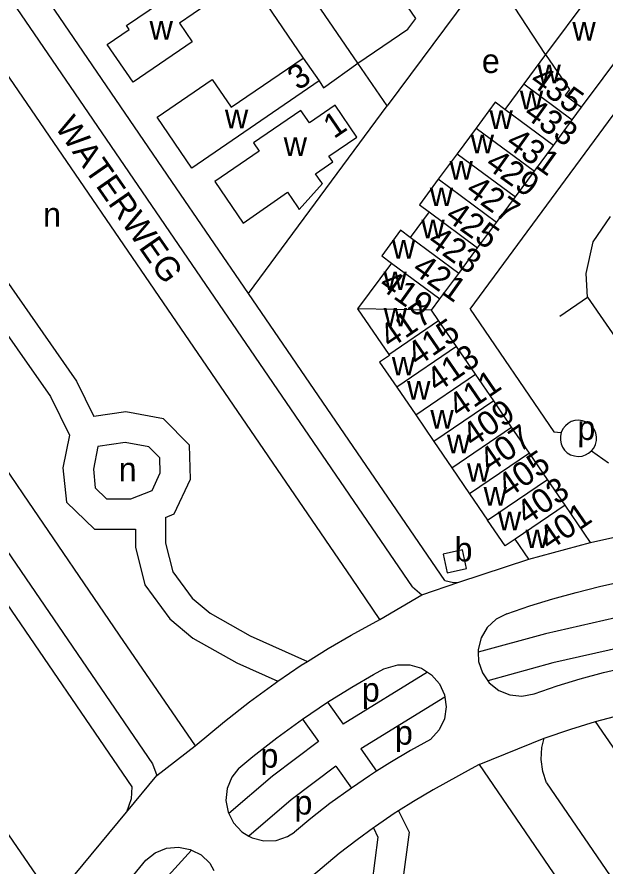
# Model space of a CAD drawing. Extents: x 154320 to 156262, y 382651 to 384180.
# Drawn here: x 155678.1 to 155775.5, y 383138.5 to 383279.2 of the extents above; entities that cross this region are included whole.
import ezdxf

# ---------------------------------------------------------------- set-up
doc = ezdxf.new("R2010")
doc.units = 0
for name, color, linetype in [('BLT_Basislijn', 7, 'Continuous'), ('BLT_Bebouwing', 7, 'Continuous'), ('BLT_Centroide', 7, 'Continuous'), ('BLT_Huisnummer', 7, 'Continuous'), ('BLT_Huisnummer_ tussenligend', 7, 'Continuous'), ('BLT_Onderdoorgang_en_onderverdeling', 7, 'Continuous'), ('BLT_Onderverdeling_panden', 7, 'Continuous'), ('BLT_Straatnaam', 7, 'Continuous'), ('BLT_Vlakafsluiter', 7, 'Continuous')]:
    doc.layers.add(name, color=color, linetype=linetype)

msp = doc.modelspace()

# ---------------------------------------------------------------- linework, layer by layer
at = {"layer": 'BLT_Basislijn'}
for p, q in [((155692.64, 383320.53), (155725.53, 383272.42)), ((155734.58, 383271.59), (155717.76, 383296.2)), ((155765.68, 383273), (155756.32, 383287.28)), ((155716.48, 383233.38), (155739.44, 383264.48)), ((155636.48, 383262.51), (155679.1, 383200.17)), ((155748.98, 383185.83), (155716.48, 383233.38)), ((155768.04, 383229.65), (155772.65, 383232.81)), ((155772.65, 383232.81), (155783.95, 383216.3)), ((155773.27, 383207.3), (155776.13, 383205.34)), ((155773.14, 383192.15), (155790.01, 383195.94)), ((155674.04, 383194.27), (155700.59, 383155.44)), ((155670.14, 383191.12), (155697.12, 383151.65)), ((155743.62, 383184.81), (155745.16, 383183.45)), ((155653.33, 383177.6), (155684.15, 383132.85)), ((155725.43, 383162.87), (155729.57, 383165.67)), ((155729.57, 383165.67), (155732.17, 383162.01)), ((155725.43, 383162.87), (155728.05, 383159.17)), ((155735.06, 383157.92), (155737.68, 383154.22)), ((155700.59, 383155.44), (155701.29, 383153.51)), ((155730.94, 383155.08), (155733.52, 383151.44)), ((155696.27, 383147.42), (155701.29, 383153.51)), ((155684.15, 383132.85), (155696.27, 383147.42)), ((155577.92, 382991.91), (155699.45, 383139.48))]:
    msp.add_line(p, q, dxfattribs=at)
for points in [[(155703.78, 383251.95), (155662.78, 383311.94)], [(155733.58, 383186.21), (155650, 383308.48)], [(155743.62, 383184.81), (155658.65, 383309.12)], [(155753.19, 383230.79), (155780.13, 383267.37), (155800.12, 383273.73)], [(155728.15, 383268.63), (155728.89, 383267.49), (155734.58, 383271.59)], [(155716.48, 383233.38), (155703.78, 383251.95)], [(155772.65, 383232.81), (155772.43, 383236.69), (155773.55, 383241.95), (155776.41, 383246.18)], [(155671.55, 383242.34), (155687.98, 383218.88), (155690.87, 383213)], [(155667.45, 383239.48), (155683.66, 383216.32), (155686.81, 383209.93), (155685.72, 383204.53), (155686.3, 383198.84), (155690.95, 383194.35), (155697.74, 383194.35)], [(155753.19, 383230.79), (155767.05, 383210.45), (155768.28, 383210.38)], [(155702.74, 383196.3), (155704.18, 383196.87), (155706.88, 383202.64), (155706.72, 383208.29), (155702.36, 383212.65), (155696.12, 383213.76), (155690.87, 383213)], [(155773.78, 383210.81), (155773.45, 383211.3), (155773, 383211.74), (155772.45, 383212.09), (155771.82, 383212.32), (155771.16, 383212.4), (155770.52, 383212.34), (155769.94, 383212.16), (155769.43, 383211.88), (155768.96, 383211.49), (155768.56, 383210.98), (155768.28, 383210.38)], [(155768.28, 383210.38), (155768.13, 383209.73), (155768.13, 383209.07), (155768.26, 383208.46), (155768.5, 383207.92)], [(155773.27, 383207.3), (155773.66, 383207.79), (155773.95, 383208.38), (155774.1, 383209.02), (155774.11, 383209.66), (155774, 383210.27), (155773.78, 383210.81)], [(155691.53, 383208.05), (155690.77, 383204.28), (155691.09, 383201.17), (155692.97, 383199.35), (155696.95, 383199.35), (155700.49, 383200.77), (155701.85, 383203.69), (155701.78, 383206.16), (155699.94, 383208), (155696.04, 383208.7), (155691.53, 383208.05)], [(155768.5, 383207.92), (155768.83, 383207.44), (155769.28, 383207.01), (155769.83, 383206.68), (155770.45, 383206.47), (155771.1, 383206.39), (155771.73, 383206.45), (155772.3, 383206.64), (155772.81, 383206.91), (155773.27, 383207.3)], [(155679.1, 383200.17), (155695.07, 383176.8)], [(155759.27, 383180.32), (155763.06, 383181.61), (155766.88, 383182.79), (155770.73, 383183.86), (155774.62, 383184.83), (155777.81, 383185.54), (155844.27, 383200.42)], [(155702.74, 383196.3), (155702.74, 383192), (155703.92, 383187.26), (155707.12, 383182.93), (155710.1, 383180.4), (155716.76, 383176.68), (155726.25, 383172.43)], [(155846.89, 383196.56), (155813.68, 383189.19), (155777.25, 383179.66), (155765.68, 383177.02), (155754.53, 383173.95)], [(155697.74, 383194.35), (155697.74, 383191.38), (155699.31, 383185.09), (155703.44, 383179.5), (155707.23, 383176.27), (155714.52, 383172.21), (155721.34, 383169.15)], [(155849.92, 383192.11), (155814.86, 383184.33), (155778.44, 383174.8), (155766.9, 383172.17), (155756.12, 383169.2)], [(155751.32, 383185.54), (155762.89, 383189.38)], [(155763.8, 383167.07), (155767.59, 383168.36), (155771.42, 383169.53), (155775.28, 383170.58), (155780.77, 383171.85), (155852.75, 383187.97)], [(155738.25, 383179.38), (155733.58, 383186.21)], [(155745.16, 383183.45), (155751.32, 383185.54)], [(155748.98, 383185.83), (155750.45, 383185.52), (155751.32, 383185.54)], [(155726.25, 383172.43), (155729.68, 383174.58), (155733.48, 383176.79), (155738.25, 383179.38)], [(155759.27, 383180.32), (155757.48, 383179.42), (155756.02, 383178.07), (155755, 383176.35), (155754.52, 383174.4), (155754.53, 383173.95)], [(155695.07, 383176.8), (155707.64, 383158.42)], [(155754.53, 383173.95), (155754.57, 383172.4), (155755.22, 383170.51), (155756.12, 383169.2)], [(155721.34, 383169.15), (155725.22, 383171.78), (155726.25, 383172.43)], [(155729.57, 383165.67), (155733.56, 383168.16), (155737.16, 383170.25), (155738.88, 383171.18)], [(155746.11, 383170.63), (155732.17, 383162.01)], [(155738.88, 383171.18), (155741.19, 383171.86), (155743.19, 383171.85), (155745.11, 383171.28), (155746.11, 383170.63)], [(155746.11, 383170.63), (155746.79, 383170.2), (155748.11, 383168.69), (155748.93, 383166.87), (155748.98, 383166.52)], [(155756.12, 383169.2), (155756.35, 383168.86), (155757.92, 383167.63), (155759.78, 383166.88), (155761.77, 383166.67), (155763.8, 383167.07)], [(155707.64, 383158.42), (155712.48, 383162.49), (155716.62, 383165.74), (155720.87, 383168.83), (155721.34, 383169.15)], [(155748.98, 383166.52), (155735.06, 383157.92)], [(155748.98, 383166.52), (155749.21, 383164.89), (155748.91, 383162.91), (155748.06, 383161.1), (155746.63, 383159.48)], [(155773.94, 383162.44), (155777.11, 383163.3), (155779.64, 383163.89)], [(155714.88, 383154.71), (155717.21, 383156.67), (155721.14, 383159.75), (155725.43, 383162.87)], [(155765.45, 383159.71), (155769.89, 383161.22), (155773.94, 383162.44)], [(155801.33, 383108.62), (155805.57, 383112.09), (155806.74, 383114.83), (155773.94, 383162.44)], [(155746.63, 383159.48), (155743.32, 383157.64), (155739.87, 383155.61), (155737.68, 383154.22)], [(155765.85, 383152.28), (155765.21, 383154.18), (155764.96, 383156.16), (155765.07, 383158.16), (155765.45, 383159.71)], [(155728.05, 383159.17), (155720.42, 383153.38), (155713.2, 383147.21)], [(155754.67, 383155.35), (155753.34, 383154.61)], [(155754.67, 383155.35), (155781.59, 383115.97), (155786.38, 383110.5), (155792.35, 383105.37), (155799.06, 383101.19), (155805.08, 383098.89), (155853.42, 383081.31)], [(155714.88, 383154.71), (155713.7, 383153.24), (155712.94, 383151.39), (155712.72, 383149.4), (155713.09, 383147.43), (155713.2, 383147.21)], [(155730.94, 383155.08), (155723.56, 383149.48), (155716.55, 383143.49)], [(155737.68, 383154.22), (155736.49, 383153.46), (155733.52, 383151.44)], [(155753.34, 383154.61), (155747.04, 383151.13), (155743.79, 383149.21), (155741.32, 383147.65)], [(155765.85, 383152.28), (155787.53, 383120.57), (155791.67, 383115.84), (155796.8, 383111.44), (155801.33, 383108.62)], [(155697.12, 383151.65), (155697.01, 383149.66), (155696.27, 383147.42)], [(155733.52, 383151.44), (155729.95, 383148.87), (155726.79, 383146.41), (155724.08, 383144.15)], [(155713.2, 383147.21), (155714, 383145.65), (155715.36, 383144.19), (155716.55, 383143.49)], [(155741.32, 383147.65), (155740.62, 383147.2), (155737.5, 383145.08), (155737.15, 383144.82)], [(155741.32, 383147.65), (155743.08, 383144.14), (155741.93, 383135.48), (155742.34, 383131.59), (155744.48, 383126.93), (155746.56, 383123.69), (155748.88, 383120.95), (155759.56, 383111.48), (155762.98, 383107.25), (155769.13, 383096.43), (155772.05, 383093.56), (155780.98, 383086.01), (155786.93, 383082.35), (155790.66, 383081.54), (155799.19, 383082.02), (155803.24, 383081.5), (155808.51, 383079.32), (155812.25, 383076.51), (155815.09, 383073.7)], [(155716.55, 383143.49), (155717.09, 383143.18), (155719.03, 383142.69), (155721.03, 383142.77), (155722.92, 383143.42), (155724.08, 383144.15)], [(155737.15, 383144.82), (155734.45, 383142.87), (155731.5, 383140.57), (155724.08, 383134.36)], [(155737.15, 383144.82), (155737.92, 383143.28), (155736.89, 383135.55), (155737.46, 383130.24), (155740.09, 383124.52), (155742.53, 383120.71), (155745.3, 383117.45), (155755.93, 383108.02), (155758.83, 383104.43), (155765.13, 383093.35), (155768.68, 383089.86), (155778.04, 383081.95), (155785.04, 383077.64), (155790.27, 383076.51), (155799.01, 383077), (155801.94, 383076.62), (155806.02, 383074.94), (155808.98, 383072.72), (155811.69, 383070.03), (155812.04, 383067.38), (155811.6, 383064.12), (155810.66, 383061.59), (155808.19, 383058.28)], [(155707.05, 383141.17), (155696.56, 383129.57), (155576.82, 382984.73)], [(155699.45, 383139.48), (155701.02, 383140.72), (155702.87, 383141.47), (155704.87, 383141.66), (155706.83, 383141.28), (155707.05, 383141.17)], [(155707.05, 383141.17), (155708.61, 383140.37), (155710.05, 383138.99), (155710.74, 383137.8)]]:
    msp.add_lwpolyline(points, dxfattribs=at)
at = {"layer": 'BLT_Bebouwing'}
for p, q in [((155773.85, 383284.08), (155765.68, 383273)), ((155753.04, 383282.83), (155739.44, 383264.48)), ((155771.65, 383264.26), (155779.84, 383275.32)), ((155725.53, 383272.42), (155728.15, 383268.63)), ((155765.68, 383273), (155762.06, 383268.12)), ((155739.44, 383264.48), (155734.58, 383271.59)), ((155762.06, 383268.12), (155758.93, 383263.91)), ((155770.1, 383262.17), (155771.65, 383264.26)), ((155766.98, 383257.95), (155770.1, 383262.17)), ((155754.18, 383260.82), (155751.02, 383256.55)), ((155763.84, 383253.69), (155766.98, 383257.95)), ((155751.02, 383256.55), (155747.91, 383252.33)), ((155760.68, 383249.41), (155763.84, 383253.69)), ((155757.56, 383245.19), (155760.68, 383249.41)), ((155746.38, 383246.91), (155743.26, 383242.69)), ((155754.42, 383240.94), (155757.56, 383245.19)), ((155751.31, 383236.74), (155754.42, 383240.94)), ((155740.14, 383238.45), (155734.53, 383230.85)), ((155748.18, 383232.51), (155751.31, 383236.74)), ((155746.79, 383230.63), (155748.18, 383232.51)), ((155734.53, 383230.85), (155739.7, 383223.29)), ((155747.96, 383228.95), (155746.79, 383230.63)), ((155750.93, 383224.61), (155747.96, 383228.95)), ((155754.05, 383220.04), (155750.93, 383224.61)), ((155757.1, 383215.59), (155754.05, 383220.04)), ((155760.06, 383211.25), (155757.1, 383215.59)), ((155744.17, 383213.27), (155747.17, 383208.87)), ((155763.03, 383206.92), (155760.06, 383211.25)), ((155747.17, 383208.87), (155750.13, 383204.53)), ((155766, 383202.58), (155763.03, 383206.92)), ((155750.13, 383204.53), (155753.09, 383200.2)), ((155768.93, 383198.3), (155766, 383202.58)), ((155753.09, 383200.2), (155756.05, 383195.86)), ((155773.14, 383192.15), (155768.93, 383198.3)), ((155762.89, 383189.38), (155760.62, 383192.69)), ((155762.89, 383189.38), (155773.14, 383192.15))]:
    msp.add_line(p, q, dxfattribs=at)
for points in [[(155734.58, 383271.59), (155742.87, 383277.18), (155744.17, 383279), (155741.52, 383282.89), (155742.43, 383283.52), (155739.81, 383287.34), (155749.57, 383293.99), (155754.23, 383287.14), (155752.82, 383286.19), (155753.19, 383285.64), (155751.99, 383284.39), (155753.04, 383282.83)], [(155701.33, 383262.63), (155710.46, 383268.89), (155713.62, 383264.27), (155725.53, 383272.42)], [(155728.15, 383268.63), (155707.06, 383254.19)], [(155758.93, 383263.91), (155757.35, 383265.12), (155754.18, 383260.82)], [(155707.06, 383254.19), (155701.33, 383262.63)], [(155747.91, 383252.33), (155744.77, 383248.09), (155746.38, 383246.91)], [(155743.26, 383242.69), (155741.66, 383243.88), (155738.53, 383239.64), (155740.14, 383238.45)], [(155739.7, 383223.29), (155739.81, 383223.14), (155738.19, 383222.03), (155741.03, 383217.86)], [(155741.03, 383217.86), (155744.17, 383213.27)], [(155760.62, 383192.69), (155758.97, 383191.57), (155756.05, 383195.86)]]:
    msp.add_lwpolyline(points, dxfattribs=at)
for points in [[(155693.07, 383274.69), (155696.7, 383277.17), (155696.26, 383277.81), (155709.26, 383286.67), (155711.83, 383282.87), (155705.05, 383278.22), (155707.15, 383275.12), (155697.37, 383268.44)], [(155725.12, 383263.72), (155717.28, 383258.36), (155718.22, 383257.01), (155710.91, 383251.97), (155715.61, 383245.07), (155722.95, 383250.17), (155724.6, 383247.75), (155724.88, 383247.34), (155728.71, 383251.62), (155728.45, 383251.96), (155727.56, 383253.25), (155730.46, 383255.24), (155729.75, 383256.16), (155734.41, 383259.33), (155730.83, 383264.59), (155726.55, 383261.67)], [(155748.73, 383190.21), (155749.37, 383187.13), (155752.59, 383187.81), (155751.93, 383190.89)]]:
    msp.add_lwpolyline(points, close=True, dxfattribs=at)
at = {"layer": 'BLT_Onderdoorgang_en_onderverdeling'}
for p, q in [((155765.68, 383273), (155769.63, 383267.19)), ((155769.63, 383267.19), (155768.94, 383266.26)), ((155768.94, 383266.26), (155771.65, 383264.26))]:
    msp.add_line(p, q, dxfattribs=at)
at = {"layer": 'BLT_Onderverdeling_panden'}
for p, q in [((155762.06, 383268.12), (155770.1, 383262.17)), ((155766.98, 383257.95), (155758.93, 383263.91)), ((155754.18, 383260.82), (155763.84, 383253.69)), ((155751.02, 383256.55), (155760.68, 383249.41)), ((155757.56, 383245.19), (155747.91, 383252.33)), ((155746.38, 383246.91), (155754.42, 383240.94)), ((155751.31, 383236.74), (155743.26, 383242.69)), ((155740.14, 383238.45), (155748.18, 383232.51)), ((155746.79, 383230.63), (155734.53, 383230.85)), ((155739.7, 383223.29), (155747.96, 383228.95)), ((155750.93, 383224.61), (155741.03, 383217.86)), ((155744.17, 383213.27), (155754.05, 383220.04)), ((155757.1, 383215.59), (155747.17, 383208.87)), ((155750.13, 383204.53), (155760.06, 383211.25)), ((155763.03, 383206.92), (155753.09, 383200.2)), ((155756.05, 383195.86), (155766, 383202.58)), ((155768.93, 383198.3), (155760.62, 383192.69))]:
    msp.add_line(p, q, dxfattribs=at)
at = {"layer": 'BLT_Vlakafsluiter'}
for p, q in [((155738.25, 383179.38), (155745.16, 383183.45)), ((155754.67, 383155.35), (155765.45, 383159.71)), ((155701.29, 383153.51), (155707.64, 383158.42))]:
    msp.add_line(p, q, dxfattribs=at)

# ---------------------------------------------------------------- texts
at = {"layer": 'BLT_Centroide'}
for s, p in [('w', (155700.08, 383275.46)), ('w', (155770.12, 383275.32)), ('e', (155755.12, 383269.94)), ('w', (155764.34, 383268.25)), ('w', (155761.42, 383263.94)), ('w', (155712.56, 383260.79)), ('w', (155756.39, 383260.67)), ('w', (155722.3, 383256.21)), ('w', (155753.27, 383256.64)), ('w', (155749.77, 383252.27)), ('w', (155746.5, 383247.88)), ('n', (155682.44, 383244.49)), ('w', (155745.1, 383242.56)), ('w', (155740.23, 383239.19)), ('w', (155738.82, 383233.97)), ('w', (155738.86, 383227.93)), ('w', (155740.21, 383219.83)), ('w', (155742.74, 383215.81)), ('w', (155746.6, 383211.01)), ('w', (155749.35, 383206.91)), ('n', (155694.96, 383202.26)), ('w', (155752.67, 383202.19)), ('w', (155755.42, 383198.25)), ('w', (155757.79, 383194.16)), ('b', (155750.6, 383188.99)), ('w', (155762.35, 383191.21)), ('p', (155735.24, 383165.75)), ('p', (155740.72, 383158.63)), ('p', (155718.44, 383154.82)), ('p', (155724.08, 383147.05))]:
    msp.add_text(s, height=4, dxfattribs=at).set_placement(p)
msp.add_text('p', height=4, rotation=359.5, dxfattribs=at).set_placement((155770.94, 383209.14))
at = {"layer": 'BLT_Huisnummer'}
for s, rotation, p in [('3', 34.3525, (155724.69, 383266.94)), ('435', 324.4158, (155762.85, 383268.22)), ('1', 34.3525, (155730.62, 383258.95)), ('431', 324.4158, (155758.88, 383257.91)), ('427', 324.4158, (155752.24, 383250.02)), ('423', 324.4158, (155745.92, 383241.63)), ('419', 324.4158, (155737.86, 383234.43)), ('415', 34.4158, (155744.45, 383221.19)), ('411', 34.4158, (155751.3, 383212.67)), ('407', 34.4158, (155756.45, 383203.61)), ('401', 34.4158, (155766.3, 383190.67))]:
    msp.add_text(s, height=4, rotation=rotation, dxfattribs=at).set_placement(p)
at = {"layer": 'BLT_Huisnummer_ tussenligend'}
for s, rotation, p in [('433', 324.4158, (155761.84, 383262.79)), ('429', 324.4158, (155755.49, 383254.39)), ('425', 324.4158, (155748.86, 383245.75)), ('421', 324.4158, (155743.37, 383236.97)), ('417', 34.4158, (155739.95, 383224.17)), ('413', 34.4158, (155747.69, 383216.9)), ('409', 34.4158, (155753.61, 383207.77)), ('405', 34.4158, (155759.43, 383199.37)), ('403', 34.4158, (155762.59, 383194.9))]:
    msp.add_text(s, height=4, rotation=rotation, dxfattribs=at).set_placement(p)
at = {"layer": 'BLT_Straatnaam'}
msp.add_text('WATERWEG', height=4, rotation=304.8259, dxfattribs=at).set_placement((155684.27, 383261.04))

doc.saveas('drawing.dxf')
